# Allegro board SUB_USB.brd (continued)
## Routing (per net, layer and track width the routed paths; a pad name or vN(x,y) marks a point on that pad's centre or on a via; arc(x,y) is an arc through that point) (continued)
USB_C1_AUX_DC_N: length 3
  BOTTOM w0.097: U2.32 12.53,42.67 12.44,42.76 12.44,43.1 12.57,43.23 12.57,43.83 12.76,44.02 C162.2 R210.2
USB_C1_AUX_DC_P: length 3
  BOTTOM w0.097: U2.31 12.18,42.7 12.26,42.78 12.26,43.18 12.39,43.31 12.39,43.83 12.2,44.02 C161.2 R211.1
USB_C1_AUX_N: length 26.6
  IN4 w0.097: v1(6.66,26.47) 6.39,26.2 5.92,26.2 5.44,26.68 5.44,33.02 5.87,33.45 7.91,33.45 8.74,34.29 8.74,34.89 10.52,36.67 10.52,41.49 10.91,41.88 11.67,41.88 12.52,42.73 12.52,43.64 12.62,43.74 v1(13.11,43.74)
  BOTTOM w0.097: v1(6.66,26.47) 6.38,26.19 5.3,26.19 5.14,26.35 J13.19 ; C162.1 13.21,43.84 v1(13.11,43.74)
USB_C1_AUX_P: length 26.6
  IN4 w0.097: v1(11.84,43.74) 12.32,43.26 12.32,42.82 11.59,42.09 10.83,42.09 10.32,41.58 10.32,36.75 8.54,34.97 8.54,34.37 7.82,33.65 5.79,33.65 5.24,33.1 5.24,26.59 5.83,26 6.39,26 v1(6.66,25.73)
  BOTTOM w0.097: v1(6.66,25.73) 6.38,26.01 5.3,26.01 5.14,25.85 J13.18 ; C161.1 11.75,43.84 v1(11.84,43.74)
USB_C1_CC1: length 65.3
  TOP w0.203: R91340.2 18.96,56.82 18.86,56.92 C23.1 18.86,58.08 D2746.1
  TOP w0.381: v1(19.12,59.14) D2746.1
  IN4 w0.508: v1(19.12,59.14) 19.12,58.89 17.81,57.58 14.12,57.58 13.36,56.82 9.56,56.82 3.84,51.1 3.84,41.97 2.95,41.08 2.95,22.39 5.74,19.6 7.01,19.6 7.91,20.5 10.45,20.5 12.3,18.64 v1(12.3,17.43)
  BOTTOM w0.203: v1(12.3,17.43) 12.37,17.43 13,16.8 U9.28
USB_C1_CC1_C: length 42.1
  TOP w0.178: R91340.1 v1(18.96,55.55) 18.45,55.04 17.73,55.04 17.49,54.81 U8.4
  TOP w0.203: R91346.2 v1(15.53,59.23)
  TOP w0.254: J11.A5 42.01,53.05 v1(41.98,53.08)
  BOTTOM w0.508: v1(41.98,53.08) 40.93,52.02 40.93,50.21 39.53,48.82 36.99,48.82 36.74,49.07 30.89,49.07 29.98,49.99 29.98,52.14 26.58,55.55 v1(18.96,55.55) 18.96,55.24 18.45,54.74 17.23,54.74 15.74,56.23 15.74,58.39 15.53,58.6 v1(15.53,59.23)
USB_C1_CC2: length 67
  TOP w0.203: R91341.2 18.19,56.74 18.29,56.84 C24.1 18.29,58.08 D2745.1
  TOP w0.381: v1(18.03,59.19) D2745.1
  IN4 w0.508: v1(18.03,59.19) 18.03,58.98 17.52,58.47 13.75,58.47 12.99,57.71 9.3,57.71 2.95,51.36 2.95,42.34 2.06,41.45 2.06,22.02 5.37,18.71 7.38,18.71 8.28,19.61 10.08,19.61 11.34,18.35 11.34,17.19 11.84,16.69 12.61,16.69 13.12,17.19 v1(13.12,17.43)
  BOTTOM w0.198: U9.29 13.4,17.2 13.17,17.43 v1(13.12,17.43)
USB_C1_CC2_C: length 53.1
  TOP w0.178: U8.5 17.22,55.21 17.56,55.55
  TOP w0.203: R91341.1 18.19,55.6 v1(18.14,55.55) ; R91345.2 v1(16.29,59.23)
  TOP w0.508: 17.56,55.55 v1(18.14,55.55)
  BOTTOM w0.508: v1(16.29,59.23) 16.54,58.98 16.54,56.56 17.56,55.55 v1(18.14,55.55) 18.14,55.88 18.7,56.44 26.98,56.44 30.79,52.63 30.79,50.32 31.23,49.88 37.07,49.88 37.33,49.62 39.19,49.62 40.04,50.47 40.04,52.25 39.15,53.14 39.15,55.04 41.05,56.95 41.05,58.09 41.82,58.85 45.29,58.85 45.8,58.34 45.8,55.21 45.19,54.6 J11.B5
USB_C1_IBUS_N: length 19.7
  TOP w0.381: R226.1 23.15,13.13 22.38,12.37 v1(22.38,12.11)
  BOTTOM w0.203: 15.49,11.82 15.62,11.95 15.62,12.84 15.69,12.91 U9.17
  BOTTOM w0.381: 15.49,11.82 C189.2 15.49,9.99 15.56,9.92 C1013.1 15.08,8.71 15.08,8.17 15.97,7.29 21.67,7.29 22.38,8.01 v1(22.38,12.11)
USB_C1_IBUS_P: length 20.5
  TOP w0.381: R224.2 v1(23.15,12.11)
  BOTTOM w0.203: U9.18 15.29,12.38 14.89,11.99
  BOTTOM w0.381: v1(23.15,12.11) 23.15,11.73 22.89,11.48 22.89,7.8 21.88,6.78 15.76,6.78 14.57,7.96 14.57,8.71 C1006.1 14.09,9.92 14.29,10.12 C189.1 14.89,11.32 14.89,11.99
USB_C1_INT_G_ODL: length 3.7
  TOP w0.109: Q1.1 36.36,45.01 36.13,44.78 R25.2 35.37,44.78 35.06,44.48 34.09,44.48 34.01,44.55 U7.5
USB_C1_INT_ODL: length 71.3
  TOP w0.109: Q1.3 38.64,45.52 v1(38.89,45.77)
  IN1 w0.097: v1(38.89,45.77) 37.88,46.79 29.62,46.79 26.85,44.01 20.34,44.01 17.94,46.4 11.72,46.4 7.91,42.59 7.91,39.04 5.37,36.5 5.37,25.7 v1(6,25.07)
  BOTTOM w0.114: J13.16 5.28,24.85 5.49,25.07 v1(6,25.07) 6.13,25.07 6.26,24.94 6.89,24.94 8.16,23.67 8.16,17.7 9.05,16.81 12.33,16.81 12.79,16.35 13.41,16.35 13.46,16.4 U9.27
USB_C1_ML0_C_N: length 2.6
  BOTTOM w0.097: C1032.2 8.29,38.11 8.42,38.11 9.09,38.78 9.61,38.78 9.69,38.86 U2.18
USB_C1_ML0_C_P: length 2.6
  BOTTOM w0.097: U2.17 9.69,38.51 9.61,38.6 9.17,38.6 8.5,37.93 8.29,37.93 C146.2
USB_C1_ML0_N: length 3.8
  BOTTOM w0.097: J13.40 5.14,36.85 5.3,36.69 5.43,36.69 6.85,38.11 7.27,38.11 C1032.1
USB_C1_ML0_P: length 3.8
  BOTTOM w0.097: J13.39 5.14,36.35 5.3,36.51 5.51,36.51 6.93,37.93 7.27,37.93 C146.1
USB_C1_ML1_C_N: length 2.4
  BOTTOM w0.097: C1034.2 8.29,39.64 8.75,39.64 8.95,39.83 9.61,39.83 9.69,39.91 U2.21
USB_C1_ML1_C_P: length 2.4
  BOTTOM w0.097: U2.20 9.69,39.56 9.61,39.65 9.02,39.65 8.83,39.45 8.29,39.45 C1033.2
USB_C1_ML1_N: length 3.8
  BOTTOM w0.097: J13.43 5.14,38.35 5.3,38.19 5.43,38.19 6.88,39.64 7.27,39.64 C1034.1
USB_C1_ML1_P: length 3.8
  BOTTOM w0.097: J13.42 5.14,37.85 5.3,38.01 5.51,38.01 6.96,39.45 7.27,39.45 C1033.1
USB_C1_ML2_C_N: length 2.4
  BOTTOM w0.097: U2.24 9.69,40.96 9.61,40.88 8.79,40.88 8.51,41.16 8.29,41.16 C1036.2
USB_C1_ML2_C_P: length 2.4
  BOTTOM w0.097: C1035.2 8.29,40.98 8.43,40.98 8.71,40.7 9.61,40.7 9.69,40.61 U2.23
USB_C1_ML2_N: length 3.8
  BOTTOM w0.097: J13.46 5.14,39.85 5.3,39.69 5.43,39.69 6.9,41.16 7.27,41.16 C1036.1
USB_C1_ML2_P: length 3.8
  BOTTOM w0.097: C1035.1 7.27,40.98 6.98,40.98 5.51,39.51 5.3,39.51 5.14,39.35 J13.45
USB_C1_ML3_C_N: length 3
  BOTTOM w0.097: U2.26 9.69,41.66 9.61,41.58 9.17,41.58 8.74,42.01 8.74,42.48 8.54,42.69 8.29,42.69 C1038.2
USB_C1_ML3_C_P: length 3
  BOTTOM w0.097: U2.25 9.69,41.31 9.61,41.4 9.1,41.4 8.56,41.93 8.56,42.4 8.46,42.5 8.29,42.5 C1037.2
USB_C1_ML3_N: length 3.8
  BOTTOM w0.097: C1038.1 7.27,42.69 6.93,42.69 5.43,41.19 5.3,41.19 5.14,41.35 J13.49
USB_C1_ML3_P: length 3.8
  BOTTOM w0.097: J13.48 5.14,40.85 5.3,41.01 5.51,41.01 7,42.5 7.27,42.5 C1037.1
USB_C1_RX1_CON_N: length 8
  TOP w0.097: v1(40.8,48.9) 41.08,48.61 41.08,48.36 40.89,48.17 R220.1 40.89,47.63 40.79,47.54 C168.2
  IN1 w0.097: v1(40.8,48.9) 40.86,48.96 40.86,50.18 42.37,51.69 42.75,51.69 42.96,51.9 44.5,51.9 J11.B10
USB_C1_RX1_CON_P: length 8
  TOP w0.097: v1(41.54,48.9) 41.26,48.62 41.26,48.35 41.45,48.17 R221.1 41.45,47.66 41.55,47.56 C169.2
  IN1 w0.097: J11.B11 44.5,51.7 43.05,51.7 42.83,51.48 42.45,51.48 41.06,50.1 41.06,49.4 41.16,49.3 41.45,49.3 41.54,49.2 v1(41.54,48.9)
USB_C1_RX1_L_N: length 42.6
  TOP w0.097: v1(40.8,43.7) 41.08,43.98 41.08,44.17 40.92,44.33 D7.9 D7.2 40.92,45.94 41.08,46.1 41.08,46.53 C168.1
  IN1 w0.097: v1(40.8,43.7) 41.05,43.7 41.14,43.6 41.14,43.45 40.87,43.18 35.89,43.18 34.67,41.96 27.3,41.96 26.49,41.15 20.78,41.15 12.37,32.74 11.92,32.74 11.8,32.86 11.8,33.18 11.71,33.28 v1(11.42,33.28)
  BOTTOM w0.097: U2.3 13.23,35.25 13.31,35.17 13.31,34.42 11.89,33 11.7,33 v1(11.42,33.28)
USB_C1_RX1_L_P: length 42.6
  TOP w0.097: v1(41.54,43.7) 41.26,43.98 41.26,44.17 41.42,44.33 D7.10 D7.1 41.42,45.94 41.26,46.1 41.26,46.53 C169.1
  IN1 w0.097: v1(11.42,32.53) 12.45,32.53 20.86,40.94 26.58,40.94 27.39,41.76 34.75,41.76 35.97,42.98 40.95,42.98 41.35,43.37 41.35,43.51 v1(41.54,43.7)
  BOTTOM w0.097: v1(11.42,32.53) 11.7,32.82 11.97,32.82 13.49,34.34 13.49,35.17 13.58,35.25 U2.2
USB_C1_RX2_CON_N: length 12.7
  TOP w0.097: J11.A10 42.27,55.55 42.11,55.71 39.18,55.71 36.54,53.07 36.54,50.15 36.14,49.74 35.77,49.74 35.58,49.55 R222.1 34.93,49.55 34.83,49.45 C172.2
USB_C1_RX2_CON_P: length 12.7
  TOP w0.097: C173.2 34.83,50.21 34.93,50.12 R223.1 35.58,50.12 35.77,49.93 36.06,49.93 36.35,50.22 36.35,53.14 39.1,55.89 42.11,55.89 42.27,56.05 J11.A11
USB_C1_RX2_L_N: length 38
  TOP w0.097: v1(9.7,33.55) 9.8,33.65 10.53,33.65 11.03,34.15 14.08,34.15 16.16,36.24 16.16,39.55 18.14,41.52 19.16,41.52 20.68,43.04 26.78,43.04 30.7,46.96 30.7,49.05 31.4,49.75 31.58,49.75 31.74,49.6 D8.5 D8.6 33.35,49.6 33.51,49.75 33.8,49.75 C172.1
  BOTTOM w0.097: U2.8 11.48,35.25 11.39,35.17 11.39,34.47 10.76,33.83 9.98,33.83 v1(9.7,33.55)
USB_C1_RX2_L_P: length 38
  TOP w0.097: C173.1 33.82,49.94 33.51,49.94 33.35,50.09 D8.7 D8.4 31.74,50.09 31.58,49.94 31.32,49.94 30.51,49.13 30.51,47.04 26.7,43.23 20.61,43.23 19.08,41.71 18.06,41.71 15.98,39.62 15.98,36.31 14,34.34 10.95,34.34 10.45,33.84 10.16,33.84 10.08,33.91 10.08,34.2 9.99,34.3 v1(9.7,34.3)
  BOTTOM w0.097: v1(9.7,34.3) 9.98,34.02 10.68,34.02 11.21,34.54 11.21,35.17 11.13,35.25 U2.9
USB_C1_SBU1_C: length 44.1
  TOP w0.109: U8.1 17.37,53.6 18.1,52.88 v1(18.45,52.88) 18.57,52.75 R27325.1 ; J11.A8 v1(41.94,54.55)
  BOTTOM w0.114: v1(41.94,54.55) 42.31,54.55 42.83,54.02 42.83,50.85 42.58,50.6 42.58,49.33 42.83,49.07 42.83,48.56 41.94,47.67 32.29,47.67 31.78,48.18 30.77,48.18 26.58,43.99 21.88,43.99 18.19,47.67 18.19,52.63 v1(18.45,52.88)
USB_C1_SBU1_U: length 10
  TOP w0.109: U8.15 13.2,53.6 13.06,53.47 13.06,53.31 14.26,52.12 14.26,45.52 v1(14.13,45.39)
  BOTTOM w0.114: R15.2 14,45.26 v1(14.13,45.39)
USB_C1_SBU2_C: length 44.8
  TOP w0.109: R27288.1 18.7,53.26 v1(18.45,53.52) 17.94,53.52 17.45,54 U8.2
  BOTTOM w0.114: v1(18.45,53.52) 18.32,53.52 17.94,53.14 17.94,47.59 21.79,43.74 26.7,43.74 30.89,47.93 31.7,47.93 32.2,47.42 42.07,47.42 43.59,48.94 45.24,48.94 45.75,49.45 45.75,52.05 J11.B8
USB_C1_SBU2_U: length 12.2
  TOP w0.109: U8.14 13.24,54 12.83,53.59 12.83,53.21 14.02,52.02 14.02,46.04 13.67,45.69 13.67,45.08 13.88,44.88 14.26,44.88 v1(14.76,45.39)
  BOTTOM w0.114: R16.2 v1(14.76,45.39)
USB_C1_SSRX_C_N: length 3.4
  BOTTOM w0.097: U2.11 9.67,36.41 9.59,36.49 9.43,36.49 9.33,36.39 9.33,35.64 8.58,34.88 8.29,34.88 C1040.2
USB_C1_SSRX_C_P: length 3.4
  BOTTOM w0.097: C1039.2 8.29,35.07 8.5,35.07 9.15,35.72 9.15,36.47 9.35,36.67 9.61,36.67 9.7,36.76 U2.12
USB_C1_SSRX_N: length 8.8
  TOP w0.097: v1(3.72,36.47) 3.72,36.69 3.81,36.78 4.46,36.78 6.18,35.07 6.18,34.7 6.27,34.6 v1(6.57,34.6)
  BOTTOM w0.097: C1040.1 7.27,34.88 6.85,34.88 v1(6.57,34.6) ; J13.37 4.09,35.35 3.93,35.19 3.62,35.19 3.21,35.61 3.21,36.66 3.3,36.75 3.44,36.75 v1(3.72,36.47)
USB_C1_SSRX_P: length 8.8
  TOP w0.097: v1(6.57,35.35) 6.16,35.35 4.54,36.97 3.97,36.97 v1(3.72,37.22)
  BOTTOM w0.097: C1039.1 7.27,35.07 6.86,35.07 v1(6.57,35.35) ; v1(3.72,37.22) 3.44,36.94 3.23,36.94 3.02,36.73 3.02,35.53 3.55,35.01 3.94,35.01 4.09,34.85 J13.36
USB_C1_SSTX_C_N: length 3.1
  BOTTOM w0.097: C1042.2 8.29,36.41 8.51,36.41 8.9,36.79 8.9,37.36 9.08,37.55 9.61,37.55 9.69,37.46 U2.14
USB_C1_SSTX_C_P: length 3.1
  BOTTOM w0.097: U2.15 9.69,37.81 9.61,37.73 9,37.73 8.71,37.44 8.71,36.87 8.44,36.59 8.29,36.59 C1041.2
USB_C1_SSTX_N: length 9.7
  IN1 w0.097: v1(6.57,36.13) 6.3,36.4 6.16,36.4 6,36.24 6,34.47 6.64,33.83 6.92,33.83 7.25,33.51 7.25,33.19 v1(7.55,32.88)
  BOTTOM w0.097: v1(7.55,32.88) 7.27,33.16 7.27,33.45 7.03,33.69 5.3,33.69 5.14,33.85 J13.34 ; C1042.1 7.27,36.41 6.85,36.41 v1(6.57,36.13)
USB_C1_SSTX_P: length 9.7
  IN1 w0.097: v1(6.81,32.88) 7.04,33.12 7.04,33.42 6.84,33.63 6.55,33.63 5.8,34.38 5.8,36.32 6.08,36.6 6.3,36.6 v1(6.57,36.87)
  BOTTOM w0.097: v1(6.57,36.87) 6.85,36.59 7.27,36.59 C1041.1 ; J13.33 5.14,33.35 5.3,33.51 6.95,33.51 7.09,33.37 7.09,33.16 v1(6.81,32.88)
USB_C1_TX1_CON_N: length 6.8
  TOP w0.097: J11.A3 42.27,52.05 42.11,51.89 41.9,51.89 41.09,51.08 41.09,50.39 39.47,48.76 39.47,47.44 C170.2
USB_C1_TX1_CON_P: length 6.7
  TOP w0.097: C171.2 39.75,47.26 39.65,47.36 39.65,48.69 41.28,50.31 41.28,51.01 41.98,51.71 42.11,51.71 42.27,51.55 J11.A2
USB_C1_TX1_L_N: length 31.4
  TOP w0.097: v1(38.07,44.71) 38.38,44.41 38.73,44.41 39.02,44.12 39.45,44.12 39.55,44.21 39.55,44.35 39.42,44.48 D7.6 D7.5 39.42,45.94 39.58,46.1 39.58,46.53 C170.1
  IN1 w0.097: v1(38.07,44.71) 37.79,44.71 37.69,44.61 37.69,44.38 37.59,44.29 35.76,44.29 34.07,42.59 27.05,42.59 26.24,41.78 18.79,41.78 18.53,41.53 18.53,41.3 v1(18.26,41.03)
  BOTTOM w0.097: v1(18.26,41.03) 18.54,41.31 18.54,41.4 18.42,41.52 18.14,41.52 17.07,40.45 16.01,40.45 15.55,40 15.09,40 15.01,39.91 U2.42
USB_C1_TX1_L_P: length 31.4
  TOP w0.097: v1(38.07,43.96) 38.33,44.22 38.66,44.22 38.95,43.93 39.53,43.93 39.74,44.14 39.74,44.32 39.92,44.51 D7.7 D7.4 39.92,45.94 39.76,46.1 39.76,46.53 C171.1
  IN1 w0.097: v1(38.07,43.96) 37.95,44.08 35.84,44.08 34.15,42.39 27.13,42.39 26.32,41.58 18.87,41.58 18.74,41.44 18.74,41.3 v1(19.01,41.03)
  BOTTOM w0.097: v1(19.01,41.03) 18.73,41.31 18.73,41.47 18.5,41.71 18.06,41.71 16.99,40.64 15.93,40.64 15.48,40.18 15.15,40.18 15.06,40.26 U2.41
USB_C1_TX2_CON_N: length 13.2
  TOP w0.097: v1(35.85,51.2) 35.57,51.48 35.23,51.48 35.02,51.28 34.85,51.28 C175.2
  IN1 w0.097: J11.B3 44.5,55.7 39.55,55.7 36.61,52.75 36.61,51.74 36.37,51.5 36.14,51.5 v1(35.85,51.2)
USB_C1_TX2_CON_P: length 13.1
  TOP w0.097: C176.2 34.82,51.46 34.94,51.46 35.15,51.67 35.57,51.67 v1(35.85,51.95)
  IN1 w0.097: v1(35.85,51.95) 36.09,51.7 36.28,51.7 36.41,51.82 36.41,52.84 39.47,55.9 44.5,55.9 J11.B2
USB_C1_TX2_L_N: length 29.9
  TOP w0.097: v1(18.57,42.26) 18.88,42.26 18.97,42.35 18.97,42.72 20.06,43.81 26.52,43.81 30,47.29 30,49.96 31.3,51.25 31.58,51.25 31.74,51.1 D8.2 D8.9 33.35,51.1 33.51,51.25 33.82,51.25 C175.1
  BOTTOM w0.097: v1(18.57,42.26) 18.57,42.46 18.67,42.56 19.11,42.56 19.53,42.14 19.53,40.38 18.28,39.13 15.08,39.13 15,39.21 U2.44
USB_C1_TX2_L_P: length 29.9
  TOP w0.097: C176.1 33.8,51.44 33.51,51.44 33.35,51.6 D8.10 D8.1 31.74,51.6 31.58,51.44 31.22,51.44 29.82,50.04 29.82,47.37 26.44,43.99 19.98,43.99 18.99,43 v1(18.57,43)
  BOTTOM w0.097: v1(18.57,43) 18.83,42.75 19.18,42.75 19.72,42.21 19.72,40.31 18.36,38.95 15.1,38.95 15.02,38.86 U2.45
USB_C1_USB2_L_N: length 16.5
  TOP w0.097: J11.A7 42.34,54.05 42.24,53.95 42.24,53.83 42.14,53.74 41.39,53.74 41.23,53.57 40.54,53.57 40.44,53.67 40.44,53.84 v1(40.78,54.17) ; v1(38.38,50.4) 38.1,50.12 38.1,49.87 38.19,49.77 D2741.2 38.48,49.18 38.48,47.83 L5.3
  IN1 w0.097: v1(38.38,50.4) 38.16,50.62 38.16,51 40.56,53.4 40.56,53.96 v1(40.78,54.17) 40.47,54.48 40.47,54.71 40.72,54.96 42.24,54.96 43.21,54 43.5,54 J11.B7
USB_C1_USB2_L_P: length 16.6
  TOP w0.097: L5.2 37.53,47.83 37.53,49.18 D2741.1 37.82,49.77 37.91,49.87 37.91,50.12 v1(37.63,50.4) ; J11.A6 41.47,53.55 41.3,53.39 40.46,53.39 40.25,53.59 40.25,54.06 v1(40.14,54.17)
  IN1 w0.097: v1(37.63,50.4) 37.95,50.72 37.95,51.09 40.36,53.49 40.36,53.96 v1(40.14,54.17) 40.27,54.3 40.27,54.8 40.64,55.17 42.32,55.17 43.29,54.2 J11.B6
USB_C1_USB2_N: length 36.3
  TOP w0.097: U7.2 32.19,46.08 32.08,46.18 31.95,46.18 30.77,45.01 30.5,45.01 v1(30.22,44.73)
  IN4 w0.097: v1(7.5,31.18) 7.23,31.46 7.23,31.59 7.43,31.8 11.62,31.8 13.78,33.96 16.67,33.96 17.94,35.23 17.94,35.56 23.58,41.2 25.05,41.2 28.85,45 29.95,45 v1(30.22,44.73)
  BOTTOM w0.097: J13.31 5.14,32.35 5.3,32.19 7.01,32.19 7.22,31.99 7.22,31.46 v1(7.5,31.18)
USB_C1_USB2_P: length 36.3
  TOP w0.097: v1(30.22,45.47) 30.5,45.19 30.7,45.19 31.87,46.36 32.07,46.36 32.19,46.48 U7.1
  IN4 w0.097: v1(30.22,45.47) 29.95,45.2 28.77,45.2 24.97,41.4 23.49,41.4 17.74,35.64 17.74,35.31 16.59,34.16 13.7,34.16 11.54,32 7.35,32 7.02,31.68 7.02,31.46 v1(6.75,31.18)
  BOTTOM w0.097: J13.30 5.14,31.85 5.3,32.01 6.94,32.01 7.03,31.91 7.03,31.47 v1(6.75,31.18)
USB_C1_USB2_U_N: length 4.2
  TOP w0.097: U7.7 35.94,46.08 36.27,46.4 38.06,46.4 38.28,46.62 38.28,47.21 L5.4
USB_C1_USB2_U_P: length 4.2
  TOP w0.097: U7.8 35.44,46.48 35.66,46.26 35.87,46.26 36.19,46.59 37.98,46.59 38.1,46.7 38.1,46.84 L5.1
USB_C1_VBUS_SENSE: length 4.4
  BOTTOM w0.203: U9.20 14.49,13.03 14.26,12.8 14.26,12.55 13.88,12.16
  BOTTOM w0.381: 13.88,12.16 13.42,12.16 12.99,11.73 C1024.1 12.49,11.23 12.35,11.1 R1001.2
USB_C1_VBUS_VIN_GATE: length 12.7
  TOP w0.109: v1(14.13,11.61) 16.29,9.45 20.99,9.45 21.37,9.83 23.14,9.83 R1000.2
  BOTTOM w0.114: U9.19 14.89,12.62 14.13,11.86 v1(14.13,11.61)
USB_C1_VBUS_VIN_SRC: length 11
  TOP w0.381: v1(16.42,10.08) 16.67,9.83 20.61,9.83 21.37,10.59 R1002.2
  BOTTOM w0.203: v1(16.42,10.08) 16.42,11.61 16.09,11.93 U9.16
USB_C1_VX1: length 35.6
  BOTTOM w0.203: U9.3 19.34,16.8 19.36,16.77 22.34,16.77 22.51,16.94
  BOTTOM w0.381: 23.65,17.83 23.4,17.83 22.51,16.94
  BOTTOM w0.508: v1(32.93,23.54) 33.31,23.54 34.83,22.02 34.83,19.61 31.91,16.69 25.05,16.69 24.04,15.67 C197.1
  BOTTOM w0.762: v1(32.93,22.78) 32.93,21.64 29.75,18.46 24.29,18.46 23.65,17.83
USB_C1_VX2: length 14.5
  IN4 w0.508: v1(22.13,23.29) 21.37,23.29 21.11,23.54 v1(16.54,23.54)
  BOTTOM w0.203: 18.45,19.73 18.45,19.38 17.69,18.62 U9.39
  BOTTOM w0.508: C198.1 v1(16.54,23.54)
  BOTTOM w0.762: v1(22.13,24.18) 21.88,24.18 18.45,20.75 18.45,19.73
N18245155: length 1.7
  BOTTOM w0.114: R11.1 19.08,32.56 18.96,32.43 18.45,32.43 18.29,32.28 U1.6
N18245170: length 1.9
  BOTTOM w0.114: R10.1 18.32,32.69 18.07,32.43 17.43,32.43 17.29,32.29 U1.4
N18245175: length 1.5
  BOTTOM w0.114: R12.1 17.33,32.84 17.18,32.69 17.18,32.56 16.79,32.17 U1.3
N18245180: length 1.3
  BOTTOM w0.114: U1.2 16.29,32.18 16.8,32.69 R9.1
N18245515: length 1.7
  BOTTOM w0.114: R8.1 19.84,31.16 19.69,31.01 U1.7
N18245611: length 2.2
  BOTTOM w0.114: U1.18 15.79,27.24 15.65,27.1 15.13,27.1 14.76,26.74 R6.2
N18245626: length 1.9
  BOTTOM w0.114: U1.17 16.29,27.76 16.29,27.23 15.91,26.85 15.65,26.85 15.53,26.72 R4.2
N18245631: length 1.7
  BOTTOM w0.114: U1.16 16.79,27.22 16.29,26.72 R7.2
N18245636: length 1.6
  BOTTOM w0.114: R5.2 17.05,26.85 17.29,27.09 U1.15
N18248542: length 2.1
  TOP w0.178: U8.7 15.67,56.93 15.62,56.97 R91347.2 15.62,57.89 R91346.1
N18248558: length 2.2
  TOP w0.178: R91345.1 16.19,57.89 R91348.2 16.19,56.97 16.07,56.86 U8.6
N18248699: length 1.6
  TOP w0.178: U8.3 C177.1
N18258732: length 13.6
  TOP w0.203: C7.1 14.74,35.96 v1(14.69,35.91)
  IN1 w0.508: v1(14.69,35.91) 10.78,35.91 10.17,36.52 10.17,42.49 9.68,42.98 v1(9.68,43.74)
  BOTTOM w0.152: v1(14.69,35.91) 14.58,36.03 U2.52
N18295145: length 1.4
  TOP w0.109: Q1000.4 24.93,9.58 24.8,9.45 R1000.1
N18295287: length 16.6
  TOP w0.635: Q1001.1 v1(32.8,20.2)
  BOTTOM w0.203: 23.27,16.69 22.98,16.4 U9.4
  BOTTOM w0.762: v1(32.8,20.2) 30.05,17.45 24.67,17.45 23.91,16.69 23.27,16.69
N18295291: length 10.8
  TOP w0.635: v1(21.88,25.58) 21.88,25.7 21.11,26.47 Q1008.1
  BOTTOM w0.203: U9.38 17.29,18.83 17.56,19.1 17.56,19.61
  BOTTOM w0.762: 17.56,19.61 17.56,21.26 v1(21.88,25.58)
N18295339: length 21.9
  TOP w0.635: v1(33.18,27.1) 33.18,26.38 Q1001.8
  BOTTOM w0.203: U9.2 20.86,17.2 20.99,17.32
  BOTTOM w0.381: 20.99,17.32 21.62,17.32 22.13,17.83
  BOTTOM w0.762: 22.13,17.83 24.16,19.86 29.12,19.86 31.4,22.15 31.4,25.32 v1(33.18,27.1)
N18295351: length 6.3
  TOP w0.635: Q1008.8 v1(21.88,21.09)
  BOTTOM w0.203: U9.40 18.09,18.49 18.32,18.72 18.96,18.72 19.72,19.48
  BOTTOM w0.762: 19.72,19.48 19.72,20.12 20.69,21.09 v1(21.88,21.09)
N18295373: length 1.4
  BOTTOM w0.381: R1006.1 20.97,15.67 C197.2
N18295375: length 1.4
  BOTTOM w0.381: R1007.2 16.8,21.29 C198.2
N18295448: length 1.3
  BOTTOM w0.203: U9.5 19.26,16 19.36,15.9
  BOTTOM w0.381: 19.36,15.9 R1006.2
N18295450: length 1.3
  BOTTOM w0.203: 16.8,18.85 16.89,18.75 U9.37
  BOTTOM w0.381: 16.8,18.85 R1007.1
N18295725: length 1
  BOTTOM w0.114: C1007.1 R1003.2
N18295735: length 1
  BOTTOM w0.114: C1009.1 R1005.2
N18295835: length 1.2
  BOTTOM w0.114: R1009.1 16.57,12.72 16.49,12.8 U9.15
N18295941: length 1.7
  BOTTOM w0.203: C1011.1 12.41,16 U9.26
N18296056: length 5.4
  BOTTOM w0.114: R227.1 21.62,11.35 20.61,12.37 18.45,12.37 18.09,12.73 U9.11
N18298566: length 2
  TOP w0.109: U37.8 28.04,36.61 28.15,36.5 29.12,36.5 29.14,36.53 R27304.2
N18298568: length 3.7
  TOP w0.109: U37.7 27.54,36.55 27.87,36.22 30.15,36.22 30.26,36.33 R27303.2
N18298570: length 5.2
  TOP w0.109: U37.6 27.04,36.54 27.62,35.96 30.74,35.96 31.02,36.24 R27302.2
N18298637: length 3
  TOP w0.109: U37.15 27.04,41.49 26.45,42.09 R27306.1
N18298641: length 1.8
  TOP w0.109: U37.16 26.54,40.96 26.43,41.07 26.28,41.07 26.28,41.07 R27305.1
N18310730: length 1.7
  BOTTOM w0.114: R27309.1 15.94,41.48 15.5,41.04 15.12,41.04 15.04,40.96 U2.39
N18310842: length 1.8
  BOTTOM w0.114: U2.35 13.58,42.68 13.75,42.85 14.51,42.85 TP93.1
N18310878: length 1.8
  BOTTOM w0.114: U2.37 14.58,41.9 14.89,42.21 15.65,42.21 TP95.1
N18311237: length 2.4
  BOTTOM w0.114: TP99.1 15.15,35.36 15.15,36.63 15.01,36.76 U2.51
N18311298: length 4.4
  BOTTOM w0.114: TP100.1 15.39,34.2 15.39,36.73 15,37.11 U2.50
N18311691: length 3.1
  BOTTOM w0.114: U2.33 12.88,42.8 13.43,43.36 13.88,43.36 14.26,43.74 14.26,44.15 R15.1
N18311698: length 3
  BOTTOM w0.114: U2.34 13.23,42.81 13.53,43.11 13.98,43.11 14.5,43.64 14.5,44.13 R16.1
N18311970: length 3.6
  BOTTOM w0.152: U2.49 15.07,37.46 15.82,36.71 C1031.2
  BOTTOM w0.203: R27311.2 16.03,36.25 15.94,36.34 C1031.2
  BOTTOM w0.381: R27311.2 16.03,34.86 R27310.2
N18312906: length 3.7
  BOTTOM w0.114: R84.2 17.46,39.9 17.33,40.03 16.1,40.03 15.94,39.86 C1021.2 15.43,39.57 15.42,39.56 U2.43
N18314765: length 17.1
  IN4 w0.508: v1(12,35.03) v1(14,35.03) 14.76,35.03 15.3,35.56 15.3,38.04 v1(15.43,38.16) 15.4,38.19 v1(15.4,41.58)
  BOTTOM w0.152: U2.7 11.83,35.2 v1(12,35.03) 12.18,35.21 U2.6 ; v1(10.57,35.03) 10.78,35.23 U2.10 ; U2.30 v1(11.83,43.05) ; v1(14,35.03) 13.93,35.11 U2.1 ; U2.38 15.13,41.31 v1(15.4,41.58) ; U2.13 v1(9.34,37.11) ; U2.47 v1(15.43,38.16) ; U2.16 v1(9.34,38.16)
N18322467: length 3
  BOTTOM w0.114: TP103.1 16.8,41.2 16,41.2 15.6,40.8 15.22,40.8 15.03,40.61 U2.40
N18368928: length 1.3
  TOP w0.109: R27331.1 21.62,39.29 21.55,39.22 U1001.3
N18394207: length 1.5
  BOTTOM w0.114: U1.14 17.79,26.74 17.81,26.72 R27332.2
N18445576: length 1.7
  BOTTOM w0.114: TP106.1 8.03,50.6 R37.2 R27329.2
N18445729: length 2.4
  BOTTOM w0.114: J12.17 6.84,53.85 TP109.1

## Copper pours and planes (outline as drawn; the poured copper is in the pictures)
3V3_SW on TOP (solid shape): 11.21,55.17 11.21,53.64 11.97,52.88 11.97,50.6 11.84,50.47 8.41,50.47 8.29,50.6 8.29,54.79 8.8,55.29 9.99,55.29 11.08,55.29
5V_SW on TOP (solid shape): 32.29,31.67 32.29,29.77 32.16,29.64 31.4,29.64 30.89,29.13 30.89,28.62 30.77,28.5 27.97,28.5 27.85,28.62 27.85,33.2 27.97,33.32 30.64,33.32
GND on TOP (solid shape): outline of 191 points within 31.05,46.02 40.67,51.64
GND on TOP (solid shape): outline of 4985 points within 0.51,0.51 48.26,60.09
GND on BOTTOM (solid shape): 16.59,17.89 16.66,17.89 16.66,17.76 18,17.76 18.26,17.51 18.26,13.96 18.13,13.83 14.57,13.83 14.32,14.08 14.32,17.64 14.45,17.76 16.32,17.76 16.32,17.89 16.39,17.89 16.39,18.46 16.59,18.46
GND on BOTTOM (solid shape): 16.95,37.49 17.01,37.45 17.08,37.43 17.23,37.43 17.23,37.3 17.24,37.3 17.29,37.27 17.28,37.21 17.18,37.11 17.18,36.38 17.13,36.29 17.03,36.29 16.92,36.33 16.81,36.35 16.61,36.31 16.45,36.19 16.39,36.16 16.31,36.19 16.29,36.21 16.26,36.22 16.26,36.25 16.24,36.35 16.18,36.42 16.17,36.44 16.17,37.64 16.79,37.64
GND on BOTTOM (solid shape): 11.84,45.52 11.84,44.82 11.82,44.75 11.75,44.72 11.68,44.71 11.6,44.69 11.52,44.69 11.52,44.64 11.43,44.52 11.4,44.37 11.4,43.84 11.4,43.74 11.09,43.74 10.94,43.88 10.95,43.95 10.96,43.99 10.85,44.25 10.59,44.37 10.57,44.37 10.45,44.5 10.45,45.39 10.61,45.55 10.86,45.55 11.02,45.57 11.16,45.64 11.72,45.64
GND on BOTTOM (solid shape): 20.86,20.12 20.86,18.57 20.34,18.04 20.28,18.06 20.25,18.06 19.95,18.06 19.84,18.03 19.75,17.95 19.74,17.92 19.45,17.92 19.37,17.9 19.29,17.85 19.26,17.83 18.58,17.83 18.32,18.09 18.32,18.39 18.42,18.49 18.96,18.49 19.01,18.5 19.09,18.53 19.12,18.56 19.56,19 19.59,18.99 19.65,18.98 19.72,18.97 20.08,19.12 20.23,19.48 20.23,19.9 20.56,20.24 20.73,20.24
GND on BOTTOM (solid shape): 18.03,42.98 18.13,43.01 18.2,42.93 18.23,42.83 18.3,42.74 18.31,42.71 18.3,42.68 18.24,42.58 18.23,42.46 18.23,42.41 18.2,42.33 18.19,42.26 18.2,42.22 18.2,42.18 18.18,42.09 18.1,42.05 18.06,42.05 17.92,42.03 17.81,41.95 17.64,41.78 17.56,41.75 17.49,41.8 17.35,41.92 17.18,41.96 16.91,41.85 16.8,41.58 16.8,41.54 16.81,41.47 16.72,41.38 16.36,41.38 16.29,41.45 16.29,42.45 16.29,42.49 16.29,42.72 16.44,42.87 17.2,42.87 17.36,42.76 17.56,42.72 17.75,42.76 17.92,42.87
GND on BOTTOM (solid shape): outline of 231 points within 21.68,36.27 31.84,42.54
GND on BOTTOM (solid shape): outline of 165 points within 15.4,7.61 22.07,12.5
GND on BOTTOM (solid shape): outline of 5907 points within 0.51,0.51 48.26,60.09
GND on SGND (solid shape): 47.77,60.09 48.12,59.95 48.26,59.6 48.26,49.1 48.12,48.75 47.77,48.61 46.87,48.61 46.16,48.31 45.86,47.6 45.86,42.01 45.66,41.81 40.37,41.81 39.24,42.27 38.49,41.3 38.49,27.8 39.24,26.83 40.37,27.29 45.66,27.29 45.86,27.09 45.86,23.81 45.66,23.61 42.87,23.61 41.86,22.6 42.87,21.59 45.66,21.59 45.86,21.39 45.86,1 45.72,0.65 45.37,0.51 37.01,0.51 37.01,1.35 35,3.36 32.99,1.35 32.99,0.51 26.35,0.51 26,0.65 25.86,1 25.86,4.35 25.42,5.42 24.35,5.86 1,5.86 0.65,6 0.51,6.35 0.51,59.6 0.65,59.95 1,60.09
GND on IN1 (solid shape): 20.02,37.07 20,37.05 20,35.06 20.12,34.93 20.12,32.67 20.06,32.58 19.95,32.6 18.87,33.68 17.59,33.68 17.5,33.74 17.52,33.85 18.57,34.9 18.64,35.01 18.67,35.14 18.67,36.57 19.23,37.13 19.99,37.13
GND on IN1 (solid shape): 25.12,38.24 25.22,38.21 25.33,38.11 25.33,37.43 24.12,36.22 22.55,36.22 21.81,36.96 21.79,37.07 21.89,37.13 23.42,37.13 23.51,37.08 23.5,36.97 23.44,36.87 23.43,36.75 23.78,36.4 24.14,36.75 24.12,36.87 24.06,36.97 24.05,37.08 24.14,37.13 24.21,37.13 24.34,37.16 24.46,37.23 24.67,37.45 24.75,37.56 24.77,37.7 24.77,37.77 24.89,37.89 25,38 25.05,38.15
GND on IN1 (solid shape): 27.77,41.41 27.84,41.38 27.87,41.31 27.97,41.08 28.2,40.97 28.24,40.95 28.25,40.92 28.25,38.36 28.44,38.17 29.4,38.17 29.47,38.14 29.5,38.05 29.49,37.99 29.51,37.88 29.56,37.78 29.57,37.67 29.48,37.62 26.87,37.62 26.55,37.94 26.55,39.97 26.36,40.16 22.85,40.16 22.66,39.97 22.66,39.08 22.62,38.99 22.52,38.99 22.46,39.01 22.38,39.01 22.03,38.66 22.38,38.3 22.6,38.38 22.73,38.57 22.73,38.58 22.78,38.63 22.85,38.55 23.58,38.55 23.67,38.5 23.66,38.39 23.61,38.3 23.6,38.19 23.6,38.15 23.57,38.07 23.5,38.03 19.16,38.03 19.09,38.06 19.06,38.14 19.06,38.15 19.03,38.28 18.95,38.4 18.92,38.47 18.95,38.54 21.01,40.59 26.58,40.59 26.71,40.62 26.82,40.7 27.53,41.41
GND on IN1 (solid shape): outline of 1022 points within 5.52,24.79 18.6,43.66
GND on IN1 (solid shape): outline of 1314 points within 1.96,11.63 35.82,35.54
GND on IN1 (solid shape): outline of 3487 points within 0.51,0.51 48.26,60.09
GND on IN2 (solid shape): outline of 7947 points within 0.51,0.51 48.26,60.09
GND on IN3 (solid shape): outline of 8113 points within 0.51,0.51 48.26,60.09
GND on IN4 (solid shape): 13.65,20.73 13.65,19.61 13.67,19.47 13.75,19.36 13.86,19.25 13.8,19.2 13.75,19.2 13.5,19.1 13.39,18.85 13.42,18.71 13.5,18.59 13.53,18.52 13.5,18.45 13.42,18.33 13.39,18.2 13.4,18.14 13.41,18.09 13.38,17.99 13.28,17.96 13.2,17.98 13.12,17.99 13.05,17.98 12.98,17.97 12.89,17.99 12.86,18.07 12.86,18.64 12.81,18.85 12.69,19.03 10.85,20.88 12.17,22.2
GND on IN4 (solid shape): outline of 5153 points within 0.51,0.51 48.26,60.09
GND on IN5 (solid shape): outline of 7947 points within 0.51,0.51 48.26,60.09
PP1200_SUB_S on TOP (solid shape): 7.02,41.83 7.02,41.02 7.02,40.94 6.76,40.69 6.76,40.5 6.68,40.26 6.76,40.03 6.76,39.67 6.64,39.55 5.49,39.55 5.37,39.67 5.37,41.73 5.4,41.8 5.47,41.83 5.49,41.83 5.65,41.86 5.78,41.96 6.89,41.96
PP1200_SUB_S_R on TOP (solid shape): 11.97,46.79 11.97,44.5 11.84,44.37 11.22,44.37 11.2,44.37 10.59,44.37 9.81,44.37 9.52,44.08 9.51,44.08 9.31,43.79 9.43,43.45 9.43,43.1 9.18,42.85 9.16,42.85 8.92,42.72 8.82,42.47 8.85,42.33 8.92,42.21 8.92,40.94 8.8,40.82 7.4,40.82 7.14,41.07 7.14,44.23 7.14,44.26 7.14,46.53 7.53,46.91 11.84,46.91
PP3300_SUB_LDO_G on BOTTOM (solid shape): 14.13,51.1 14.13,50.16 13.75,49.77 13.74,49.77 13.67,49.7 13.67,48.82 13.37,48.82 13.37,49.7 13.3,49.77 13.29,49.77 12.86,50.21 12.86,51.1 12.99,51.23 14,51.23
PP3300_SUB_S on TOP (solid shape): 18.83,37.51 18.83,37.01 18.45,36.63 18.45,34.97 16.92,33.45 16.92,32.56 16.8,32.43 15.91,32.43 15.78,32.56 15.78,34.97 15.91,35.1 16.42,35.1 16.43,35.05 16.44,34.99 16.46,34.94 16.49,34.89 16.52,34.85 16.56,34.81 16.61,34.77 16.66,34.75 16.71,34.73 16.76,34.72 16.82,34.72 16.88,34.73 16.93,34.74 16.98,34.76 17.03,34.79 17.07,34.83 17.11,34.87 17.14,34.91 17.16,34.96 17.18,35.02 17.19,35.07 17.19,35.13 17.18,35.18 17.16,35.24 17.14,35.29 17.11,35.33 17.07,35.38 17.03,35.41 16.98,35.44 16.93,35.46 16.88,35.48 16.82,35.48 16.76,35.48 16.71,35.47 16.66,35.45 16.61,35.43 16.56,35.39 16.52,35.36 16.49,35.31 16.46,35.26 16.44,35.21 16.43,35.16 16.42,35.1 15.91,35.1 16.94,36.13 17.08,36.12 17.13,36.12 17.18,36.14 17.23,36.16 17.28,36.19 17.32,36.23 17.36,36.27 17.39,36.31 17.41,36.36 17.42,36.42 17.43,36.47 17.43,36.52 17.42,36.58 17.41,36.63 17.39,36.68 17.36,36.72 17.32,36.76 17.3,36.78 17.3,37.51 17.43,37.64 18.7,37.64
PP3300_SUB_S on BOTTOM (solid shape): 19.97,27.99 19.97,27.48 19.84,27.35 19.34,27.35 19.21,27.23 19.21,25.45 19.08,25.32 16.69,25.32 16.65,25.32 14.51,25.32 14.38,25.45 14.38,25.83 14.51,25.96 18.01,25.96 18.14,26.09 18.14,28.06 18.19,28.12 19.84,28.12
PP3300_SUB_S on BOTTOM (solid shape): 15.8,33.58 17.41,33.58 17.41,33.58 19.21,33.58 19.34,33.45 19.34,33.32 19.21,33.2 16.54,33.2 16.29,32.94 16.29,32.56 16.03,32.31 16.03,32.24 16.01,32.24 16.01,32.16 15.94,32.16 15.94,31.32 15.91,31.29 15.4,31.29 15.27,31.42 15.27,33.32 15.53,33.58 15.8,33.58
PP3300_SUB_S on IN1 (solid shape): 19.97,32.43 19.97,27.61 19.84,27.48 18.83,27.48 18.7,27.61 18.7,31.42 17.94,32.18 15.91,32.18 15.78,32.31 15.78,33.45 15.91,33.58 18.83,33.58
PP3300_USB_C1_G on TOP (solid shape): 37.75,45.52 37.62,45.39 36.35,45.39 36.28,45.31 36.27,45.31 36.2,45.28 36.14,45.23 36.04,45.13 35.47,45.13 35.34,45.26 35.34,45.73 35.94,45.73 36.08,45.75 36.19,45.83 36.41,46.06 37.75,46.06
PP3300_USB_C1_G on TOP (solid shape): 33.18,48.06 33.31,47.93 33.31,46.91 33.18,46.79 32.93,46.79 32.88,46.81 32.82,46.82 32.76,46.83 32.19,46.83 32.13,46.82 32.07,46.81 32.02,46.79 31.27,46.79 31.15,46.91 31.15,47.93 31.27,48.06 32.78,48.06
PP3300_USB_C1_U on BOTTOM (solid shape): 18.96,38.53 18.96,34.72 18.07,33.83 17.25,33.83 17.25,33.83 15.96,33.83 15.91,33.83 15.78,33.96 15.78,34.34 15.88,34.44 16.03,34.41 16.11,34.42 16.18,34.44 16.22,34.45 16.25,34.47 16.67,34.47 16.95,34.75 16.96,34.75 17.08,34.83 17.15,34.95 17.16,34.95 17.43,35.23 17.43,36.48 17.43,36.52 17.43,37.01 17.81,37.39 17.81,38.53 17.88,38.6 18.36,38.6 18.46,38.61 18.55,38.66 18.83,38.66
PP5000_SUB_U on TOP (solid shape): 21.5,37.51 21.5,35.61 21.62,35.48 22.38,35.48 22.51,35.36 22.51,34.85 22.38,34.72 19.95,34.72 19.87,34.75 19.85,34.83 19.85,34.85 19.81,35 19.72,35.13 19.72,37.51 19.84,37.64 21.37,37.64
PP5000_SUB_U on TOP (solid shape): 24.04,40.44 24.04,40.18 24.07,40.15 24.08,40.14 24.15,40.04 24.25,39.97 24.25,39.96 24.29,39.93 24.43,39.93 25.04,39.93 25.07,39.93 25.8,39.93 25.83,39.93 26.07,39.93 26.19,39.8 26.19,39.42 26.12,39.34 25.71,39.34 25.69,39.34 25.02,39.34 24.89,39.31 24.78,39.24 24.72,39.18 24.47,39.18 24.33,39.16 24.22,39.08 24.05,38.91 22.67,38.91 22.54,39 22.39,39.04 22.36,39.04 22.29,39.07 22.26,39.14 22.26,40.44 22.38,40.56 23.91,40.56
PP5000_SUB_U on IN1 (solid shape): 24.17,40.05 24.42,39.95 24.67,40.05 24.8,40.05 25.05,39.95 25.3,40.05 25.56,40.05 25.81,39.95 26.06,40.05 26.32,40.05 26.45,39.93 26.45,39.54 26.35,39.29 26.45,39.04 26.45,38.4 26.37,38.28 26.35,38.15 26.37,38.02 26.44,37.91 26.45,37.9 26.83,37.51 29.88,37.51 30.13,37.77 30.39,37.77 30.64,37.51 30.64,35.74 30.51,35.61 25.69,35.61 24.92,34.85 20.35,34.85 20.1,35.1 20.1,37.01 20.22,37.13 21.5,37.13 22.51,36.12 22.64,36.12 22.89,36.01 23.14,36.12 24.16,36.12 25.43,37.39 25.43,38.15 24.92,38.66 23.55,38.66 23.43,38.73 23.3,38.76 23.16,38.73 23.05,38.66 22.89,38.66 22.77,38.78 22.77,39.93 22.89,40.05
PP5000_SUB_U_R on TOP (solid shape): 24.54,34.47 24.54,29.77 24.42,29.64 22,29.64 21.75,29.89 18.57,29.89 18.45,30.02 18.45,30.77 18.45,30.8 18.45,33.32 18.72,33.59 18.79,33.58 18.83,33.58 19.1,33.69 19.21,33.96 19.21,34 19.19,34.07 19.63,34.5 19.7,34.54 19.75,34.59 22.44,34.59 22.44,34.59 24.42,34.59
PP5000_USB_A1_VBUS on TOP (solid shape): 32.16,42.34 32.16,39.42 32.04,39.29 30.53,39.29 30.49,39.29 29.74,39.29 29.73,39.3 29.65,39.33 29.56,39.34 28.89,39.34 28.87,39.34 28.43,39.34 28.35,39.42 28.35,40.96 28.38,40.98 28.61,41.32 28.38,41.67 28.35,41.69 28.35,42.34 28.48,42.47 32.04,42.47
PP5000_USB_A1_VBUS on IN1 (solid shape): outline of 744 points within 28.35,28.5 38.49,41.2
PPVAR_SYS on TOP (solid shape): 8.54,57.45 8.54,56.69 8.92,56.31 9.94,56.31 10.07,56.18 10.07,55.55 9.94,55.42 6.26,55.42 6.13,55.55 6.13,57.45 6.26,57.58 8.41,57.58
PPVAR_SYS on TOP (solid shape): 33.43,33.96 33.43,30.78 33.31,30.66 32.54,30.66 32.42,30.78 32.42,31.72 32.42,31.73 32.42,31.93 30.64,33.7 25.18,33.7 25.05,33.83 25.05,35.36 25.18,35.48 31.91,35.48
PPVAR_SYS on TOP (solid shape): 14.38,24.05 14.38,20.5 14.26,20.37 13.39,20.37 13.24,20.37 13.2,20.33 13.2,20.33 13.1,20.26 13.03,20.16 13.02,20.15 12.73,19.86 6,19.86 5.87,19.99 5.87,23.29 6,23.42 6.37,23.42 6.4,23.42 7.13,23.42 7.16,23.42 8.77,23.42 8.89,23.33 9.03,23.29 9.05,23.29 9.3,23.04 11.21,23.04 11.34,23.16 11.34,23.67 11.46,23.8 12.73,23.8 13.11,24.18 14.26,24.18
PPVAR_SYS on BOTTOM (solid shape): 3.88,23 5.02,23 5.18,23.16 7.78,23.16 7.91,23.04 7.91,15.67 7.53,15.29 3.08,15.29 2.95,15.42 2.95,17.5 4.96,17.5 4.96,17.7 4.18,17.7 4.18,17.5 2.95,17.5 2.95,18 4.96,18 4.96,18.2 4.18,18.2 4.18,18 2.95,18 2.95,18.5 4.96,18.5 4.96,18.7 4.18,18.7 4.18,18.5 2.95,18.5 2.95,19 4.96,19 4.96,19.2 4.18,19.2 4.18,19 2.95,19 2.95,19.5 4.96,19.5 4.96,19.7 4.18,19.7 4.18,19.5 2.95,19.5 2.95,20 4.96,20 4.96,20.2 4.18,20.2 4.18,20 2.95,20 2.95,20.5 4.96,20.5 4.96,20.7 4.18,20.7 4.18,20.5 2.95,20.5 2.95,21 4.96,21 4.96,21.2 4.18,21.2 4.18,21 2.95,21 2.95,21.5 4.96,21.5 4.96,21.7 4.18,21.7 4.18,21.5 2.95,21.5 2.95,22 4.96,22 4.96,22.2 4.18,22.2 4.18,22 2.95,22 2.95,22.5 4.96,22.5 4.96,22.7 4.18,22.7 4.18,22.5 2.95,22.5 2.95,23.04 3.08,23.16 3.72,23.16
PPVAR_SYS on IN1 (solid shape): outline of 574 points within 2.06,19.86 7.14,57.45
PPVAR_SYS on IN4 (solid shape): outline of 465 points within 5.75,20.16 26.32,35.99
PPVAR_SYS_R on TOP (solid shape): outline of 146 points within 10.19,24.56 21.37,31.93
PPVAR_USB_C1_VBUS on TOP (solid shape): outline of 119 points within 9.05,3.73 29.37,10.08
PPVAR_USB_C1_VBUS on TOP (solid shape): outline of 255 points within 36.99,51.74 44.48,55.42
PPVAR_USB_C1_VBUS on BOTTOM (solid shape): 10.95,12.11 10.95,9.7 10.83,9.57 9.18,9.57 9.05,9.7 9.05,12.11 9.18,12.24 10.83,12.24
PPVAR_USB_C1_VBUS on IN4 (solid shape): outline of 2846 points within 23.78,5 44.48,56.18
PPVAR_USB_C1_VIN on TOP (solid shape): 28.48,12.24 28.48,10.48 28.48,9.07 28.35,8.94 26.19,8.94 26.07,9.07 26.07,9.96 25.94,10.08 24.16,10.08 24.05,10.19 24.05,10.86 24.16,10.97 25.31,10.97 25.43,11.1 25.43,12.11 25.56,12.24 27.21,12.24 27.34,12.37 28.35,12.37
PPVAR_USB_C1_VIN_R on TOP (solid shape): 39.66,21.89 39.66,13.26 39.4,13 28.71,13 28.7,13.03 28.58,13.18 28.4,13.25 28.35,13.26 28.19,13.22 28.06,13.12 27.99,13.09 27.92,13.12 27.78,13.22 27.62,13.26 27.56,13.25 27.39,13.18 27.28,13.03 27.26,13 25.56,13 25.43,13.13 25.43,13.89 23.53,15.8 23.53,18.21 23.65,18.34 30.39,18.34 31.53,19.48 34.07,19.48 34.32,19.73 34.32,20.62 34.2,20.75 33.94,20.75 33.31,21.39 33.31,21.89 33.43,22.02 39.53,22.02
USB_C1_VX1 on TOP (solid shape): 33.05,25.2 37.62,25.2 37.75,25.07 37.75,22.4 37.62,22.27 33.31,22.27 32.93,21.89 30,21.89 29.88,22.02 29.88,25.58 30,25.7 32.54,25.7
USB_C1_VX2 on TOP (solid shape): 26.58,25.58 26.58,21.77 26.45,21.64 17.18,21.64 17.05,21.77 17.05,24.29 17.05,24.32 17.05,24.56 17.3,24.81 21.5,24.81 21.82,25.13 21.88,25.13 22.19,25.26 22.32,25.58 22.32,25.64 22.38,25.7 26.45,25.7
N18258732 on BOTTOM (solid shape): 10.19,44.75 10.19,44.01 10.19,43.97 10.19,43.24 10.19,43.1 10.23,43.07 10.23,43.06 10.3,42.96 10.4,42.89 10.41,42.88 10.45,42.85 10.69,42.85 10.83,42.71 10.83,42.09 10.7,41.96 10.31,41.96 10.22,42 10.13,42.01 9.76,42.01 9.52,42.25 9.54,42.28 9.58,42.37 9.59,42.47 9.55,42.64 9.43,42.77 9.43,43.42 9.43,43.42 9.43,44.75 9.56,44.88 10.07,44.88
N18270933 on TOP (solid shape): 32.29,29.26 32.29,28.24 32.16,28.12 31.67,28.12 31.53,28.12 31.49,28.08 31.49,28.08 31.39,28 31.31,27.91 31.31,27.9 31.02,27.61 30.39,27.61 30.26,27.74 30.26,28.12 30.39,28.24 30.89,28.24 31.15,28.5 31.15,29.01 31.53,29.39 32.16,29.39
N18271452 on TOP (solid shape): 12.48,55.17 12.48,54.42 12.48,53.64 12.35,53.52 11.59,53.52 11.34,53.77 11.34,55.17 11.46,55.29 12.35,55.29
N18314765 on TOP (solid shape): 8.41,38.53 9.94,38.53 10.07,38.4 10.07,36.12 10.32,35.86 13.79,35.86 13.79,35.86 14.13,35.86 14.26,35.74 14.26,35.1 13.84,34.69 10.95,34.69 10.83,34.66 10.72,34.59 10.17,34.59 10.12,34.62 10.05,34.64 9.99,34.65 9.86,34.65 9.8,34.67 9.73,34.68 7.53,36.88 7.53,37.39 7.43,37.49 7.29,37.6 7.12,37.64 6.96,37.61 6.83,37.51 5.87,37.51 5.62,37.77 5.62,38.91 5.75,39.04 7.91,39.04
N18314765 on TOP (solid shape): 11.57,43.47 11.7,43.38 11.84,43.36 12,43.39 12.13,43.48 12.83,43.48 13.11,43.36 13.4,43.48 13.73,43.48 14.76,43.48 15.65,42.59 15.65,39.76 15.63,39.69 15.63,39.62 15.63,37.87 15.53,37.77 14.76,37.77 14.64,37.89 14.64,38.47 14.64,38.47 14.64,41.01 14.64,41.01 14.64,41.64 14.64,41.64 14.64,41.71 14,42.34 11.46,42.34 11.34,42.47 11.34,43.36 11.46,43.48 11.56,43.48

Small or netless copper shapes (teardrops, artwork), in the pictures only: 1 on BOTTOM, 1 on IN1

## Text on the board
Ref Des/Silkscreen Bottom: MODEL:ZBM | DA0ZBMTB8A0 | REV:A | Please do not print out the lines with 0.39mils/0.01mm in width
User.Comments: 16x30 | 118.11x130 | 30x32
Ref Des/Silkscreen Top: DA0ZBMTB8A0 | MODEL:ZBM | REV:A | Please do not print out the lines with 0.39mils/0.01mm in width
DIMENSION: 48.77 | 60.6
User.8: 48.77 | 60.6
User.45: FIGURE | TYPE | Circle | Oblong | SIZE | 10.0 | 18.0 | 32.0 | 118.11 | 146.0 | 244.09 | 43.0x20.0 | 59.0x20.0 | 87.0x28.0 | 102.0x28.0 | DRILL CHART: TOP to BOTTOM | ALL UNITS ARE IN MILS | PLATED | NON-PLATED | ROTATION | - | 90.000 | 0.000 | QTY | 448 | 12 | 9 | 1 | 473 | 2 | TOTAL HOLES:
